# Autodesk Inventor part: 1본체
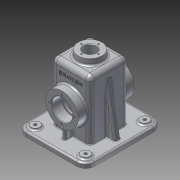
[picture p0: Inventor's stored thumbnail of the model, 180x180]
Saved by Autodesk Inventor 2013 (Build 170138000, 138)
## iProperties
Created: 2016-01
Part Number: 1본체
Material: 알루미늄 6061
Document SubType Name: Modeling
Designer: Administrator
Density: 2.71 g/cm^3
Mass: 805.142 g
Surface Area: 912.293 cm^2
Volume: 297.1 cm^3
Author: Administrator
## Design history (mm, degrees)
sketch "스케치1"
  geometry: L1 (-57.5, 65)-(57.5, 65); L2 (57.5, 65)-(57.5, -65); L3 (57.5, -65)-(-57.5, -65); L4 (-57.5, -65)-(-57.5, 65); L5 (-57.5, 65)-(57.5, -65); L6 (57.5, 65)-(-57.5, -65); 1 further point
  constraints: 12 end point, 2 midpoint, 2 parallel, 1 horizontal, 1 perpendicular
  dimensions: "d0" = 115 distance of L1.start L1.end; "d2" = 130 distance of L1.end L2.end
extrude "돌출1" new body sketch "스케치1" distance "d3" = 8; taper "d4" = 0 deg
fillet "모깎기1" dims "d5" = 15
sketch "스케치3"
  geometry: L1 (42.5, -60)-(-42.5, -60); L2 (-52.5, -50)-(-52.5, 50); L3 (-42.5, 60)-(42.5, 60); L4 (52.5, 50)-(52.5, -50); L5 (52.5, -60)-(-52.5, 60); L6 (-52.5, -60)-(52.5, 60); A1 r 10 centre (42.5, -50) between (42.5, -60) and (52.5, -50); A2 r 10 centre (42.5, 50) between (52.5, 50) and (42.5, 60); A3 r 10 centre (-42.5, 50) between (-42.5, 60) and (-52.5, 50); A4 r 10 centre (-42.5, -50) between (-52.5, -50) and (-42.5, -60); 1 further point
  constraints: 12 end point, 8 point on circle, 8 point on line, 8 tangent, 4 centre point, 3 equal radius, 2 midpoint, 2 parallel, 1 horizontal, 1 perpendicular
  dimensions: "d6" = 105 distance of L5.start L6.start; "d8" = 120 distance of L6.start L5.end; "d9" = 10 radius of A1
extrude "돌출2" join sketch "스케치3" distance "d10" = 2; taper "d11" = 0 deg
sketch "스케치7"
  geometry: L1 (-32.5, 32.5)-(32.5, 32.5); L2 (32.5, 32.5)-(32.5, -32.5); L3 (32.5, -32.5)-(-32.5, -32.5); L4 (-32.5, -32.5)-(-32.5, 32.5); L5 (-32.5, 32.5)-(32.5, -32.5); L6 (32.5, 32.5)-(-32.5, -32.5); 1 further point
  constraints: 12 end point, 2 midpoint, 2 parallel, 1 horizontal, 1 perpendicular
  dimensions: "d33" = 65 distance of L2.end L3.end; "d34" = 65 distance of L1.end L2.end
extrude "돌출4" join sketch "스케치7" distance "d35" = 100; taper "d36" = 0 deg
fillet "모깎기2" dims "d37" = 8
fillet "모깎기3" dims "d38" = 8
sketch "스케치8"
  geometry: C1 r 20 at (0, 0); 1 further point
  constraints: 1 centre point, 1 coincident
  dimensions: "d39" = 20 radius of C1
extrude "돌출5" join sketch "스케치8" distance "d40" = 10; taper "d41" = 0 deg
node "작업 평면1"
sketch "스케치10"
  geometry: L1 (-57.5, 0)-(-57.5, 8) reference; L2 (-57.5, 8)-(57.5, 8) reference; L3 (57.5, 8)-(57.5, 0) reference; L4 (52.5, 0)-(52.5, -2) reference; L5 (52.5, -2)-(-52.5, -2) reference; L6 (-52.5, -2)-(-52.5, 0) reference; L7 (-52.5, 0)-(-57.5, 0) reference; L8 (57.5, 0)-(52.5, 0) reference; C1 r 27.5 at (0, 53); 1 further point
  constraints: 1 centre point, 1 vertical alignment
  dimensions: "d44" = 55 diameter of C1; "d92" = 55 distance from line of L5 C1.centre
extrude "돌출6" join sketch "스케치10" stored distance "d45" = 10; taper "d46" = 0 deg
sketch "스케치11"
  geometry: C1 r 27.5 at (0, 0) reference; 1 further point
hole "구멍3" sketch "스케치11" at (0, 0) diameter "d47" = 30; stored, may be unused: countersink angle "d51" = 90 deg, drill point angle "d53" = 0 deg; dims "d48" = 6, "d49" = 35, "d50" = 17, "d52" = 20
sketch "스케치12"
  geometry: L1 (27.5, 27.5)-(-27.5, 27.5); L2 (-27.5, 27.5)-(-27.5, -27.5); L3 (-27.5, -27.5)-(27.5, -27.5); L4 (27.5, -27.5)-(27.5, 27.5); L5 (27.5, 27.5)-(-27.5, -27.5); L6 (-27.5, 27.5)-(27.5, -27.5); 1 further point
  constraints: 12 end point, 2 midpoint, 2 parallel, 1 horizontal, 1 perpendicular
  dimensions: "d54" = 55 distance of L2.end L3.end; "d56" = 55 distance of L3.end L1.start
extrude "돌출7" cut sketch "스케치12" distance "d57" = 105; taper "d58" = 0 deg
fillet "모깎기4" dims "d59" = 3
sketch "스케치13"
  geometry: C1 r 17.5 at (0, 0) reference; 2 further points
  constraints: 1 vertical alignment
  dimensions: "d60" = 21 distance of point (0, -21) C1.centre
hole "구멍4" sketch "스케치13" at (0, -21) diameter "d61" = 3.242; stored, may be unused: countersink angle "d65" = 90 deg, drill point angle "d67" = 118 deg; dims "d62" = 8, "d63" = 35, "d64" = 17, "d66" = 10
hole "구멍5" diameter "d73" = 21; stored, may be unused: countersink angle "d77" = 90 deg, drill point angle "d79" = 0 deg; dims "d71" = 10, "d72" = 10, "d74" = 8, "d75" = 35, "d76" = 17, "d78" = 10
feature "면 기울기1" dims angle "d80" = 5 deg
sketch "스케치14"
  geometry: C1 r 10.5 at (0, 0) reference; 1 further point
  constraints: 1 vertical alignment
  dimensions: "d81" = 14.5 distance of C1.centre point (0, -14.5)
hole "구멍6" sketch "스케치14" at (0, -14.5) diameter "d82" = 2.459; stored, may be unused: countersink angle "d86" = 90 deg, drill point angle "d88" = 118 deg; dims "d83" = 7, "d84" = 35, "d85" = 17, "d87" = 9
sketch "스케치15"
  geometry: C1 r 7.5 at (-42.5, -50); C2 r 7.5 at (42.5, -50); C3 r 7.5 at (-42.5, 50); C4 r 7.5 at (42.5, 50); A1 r 15 centre (42.5, 50) between (57.5, 50) and (42.5, 65) reference; A2 r 15 centre (-42.5, 50) between (-42.5, 65) and (-57.5, 50) reference; A3 r 15 centre (-42.5, -50) between (-57.5, -50) and (-42.5, -65) reference; A4 r 15 centre (42.5, -50) between (42.5, -65) and (57.5, -50) reference; 1 further point
  constraints: 4 centre point, 4 coincident
  dimensions: "d93" = 7.5 radius of C1; "d94" = 7.5 radius of C2; "d95" = 7.5 radius of C3; "d96" = 7.5 radius of C4
extrude "돌출8" join sketch "스케치15" distance "d97" = 3; taper "d98" = 0 deg
sketch "스케치16"
  geometry: L1 (-67, -77.5)-(-18, -77.5) reference; L2 (-15, -74.5)-(-15, -25.5) reference; L3 (-18, -22.5)-(-67, -22.5) reference; L4 (-70, -25.5)-(-70, -74.5) reference; L5 (-10, -25.5)-(-10, -74.5) reference; L6 (-18, -82.5)-(-67, -82.5) reference; L7 (-75, -74.5)-(-75, -25.5) reference; L8 (-67, -17.5)-(-18, -17.5) reference; C1 r 7.5 at (0, 0) reference; C2 r 7.5 at (-85, 0) reference; C3 r 7.5 at (-85, -100) reference; C4 r 7.5 at (0, -100) reference; C5 r 7.5 at (0, 0) reference; A1 r 3 centre (-67, -74.5) between (-70, -74.5) and (-67, -77.5) reference; A2 r 3 centre (-18, -74.5) between (-18, -77.5) and (-15, -74.5) reference; A3 r 3 centre (-18, -25.5) between (-15, -25.5) and (-18, -22.5) reference; A4 r 3 centre (-67, -25.5) between (-67, -22.5) and (-70, -25.5) reference; A5 r 8 centre (-18, -25.5) between (-10, -25.5) and (-18, -17.5) reference; A6 r 8 centre (-18, -74.5) between (-18, -82.5) and (-10, -74.5) reference; A7 r 8 centre (-67, -74.5) between (-75, -74.5) and (-67, -82.5) reference; A8 r 8 centre (-67, -25.5) between (-67, -17.5) and (-75, -25.5) reference; 1 further point
hole "구멍7" sketch "스케치16" at (-85, -100), (-85, 0), (0, 0), (0, -100) diameter "d99" = 5; stored, may be unused: countersink angle "d103" = 90 deg, drill point angle "d105" = 0 deg; dims "d100" = 5, "d101" = 35, "d102" = 17, "d104" = 9
sketch "스케치17"
  geometry: L1 (-52.5, -2)-(-52.5, 0) reference; L2 (-52.5, 0)-(-57.5, 0) reference; L3 (-57.5, 0)-(-57.5, 8) reference; L4 (-57.5, 8)-(-32.5, 8) reference; L5 (-32.5, 8)-(-32.5, 100) reference; L6 (-24.5, 108)-(-20.875, 108) reference; L7 (-20.875, 108)-(-20, 118) reference; L8 (-20, 118)-(-15.73, 118) reference; L9 (-15.73, 118)-(-15.73, 109) reference; L10 (-15.73, 109)-(-14.5, 108.261) reference; L11 (-14.5, 108.261)-(-13.271, 109) reference; L12 (-13.271, 109)-(-13.271, 118) reference; L13 (-13.271, 118)-(-10.5, 118) reference; L14 (-10.5, 118)-(-10.5, 103) reference; L15 (-10.5, 103)-(-27.5, 103) reference; L16 (-27.5, 103)-(-27.5, -2) reference; L17 (-27.5, -2)-(-52.5, -2) reference; L18 (52.5, 0)-(52.5, -2) reference; L19 (52.5, -2)-(27.5, -2) reference; L20 (27.5, -2)-(27.5, 103) reference; L21 (27.5, 103)-(10.5, 103) reference; L22 (10.5, 103)-(10.5, 118) reference; L23 (10.5, 118)-(13.271, 118) reference; L24 (13.271, 118)-(13.271, 109) reference; L25 (13.271, 109)-(14.5, 108.261) reference; L26 (14.5, 108.261)-(15.73, 109) reference; L27 (15.73, 109)-(15.73, 118) reference; L28 (15.73, 118)-(20, 118) reference; L29 (20, 118)-(20.875, 108) reference; L30 (20.875, 108)-(24.5, 108) reference; L31 (32.5, 100)-(32.5, 8) reference; L32 (32.5, 8)-(57.5, 8) reference; L33 (57.5, 8)-(57.5, 0) reference; L34 (57.5, 0)-(52.5, 0) reference; L35 (-57.5, 8)-(-42.5, 8) reference; L36 (-32.5, 100)-(-32.5, 8) reference; L37 (-32.5, 93.069)-(-47.5, 8); A1 r 8 centre (-24.5, 100) between (-24.5, 108) and (-32.5, 100) reference; A2 r 8 centre (24.5, 100) between (32.5, 100) and (24.5, 108) reference; 1 further point
  constraints: 2 end point, 2 point on line
  dimensions: "d107" = 10 distance from line of L37.end L3; "d108" = 10 deg angle of L3 L37
feature "리브1" sketch "스케치17" dims "d109" = 1, "d110" = 10, "d111" = 0, "d112" = 0, "d113" = 1, "d114" = 1
sketch "스케치18"
  geometry: L1 (0, -34.51)-(0, 0) reference; L2 (0, 0)-(49, 0) reference; L3 (49, -34.51)-(49, 0) reference; L4 (49, -92)-(49, -59.49) reference; L5 (49, -92)-(82, -92) reference; L6 (82, -92)-(82, -100) reference; L7 (82, -100)-(77, -100) reference; L8 (77, -100)-(77, -102) reference; L9 (77, -102)-(-28, -102) reference; L10 (-28, -102)-(-28, -100) reference; L11 (-28, -100)-(-33, -100) reference; L12 (-33, -100)-(-33, -92) reference; L13 (-33, -92)-(0, -92) reference; L14 (0, -92)-(49, -92) reference; L15 (0, -92)-(0, -59.49) reference; L16 (44.5, 18)-(4.5, 18) reference; L17 (-8, 0)-(-8, -92) reference; C1 r 17.5 at (24.5, -47) reference; A1 r 27.5 centre (24.5, -47) between (49, -34.51) and (0, -34.51) reference; A2 r 27.5 centre (24.5, -47) between (49, -59.49) and (49, -34.51) reference; A3 r 27.5 centre (24.5, -47) between (0, -59.49) and (49, -59.49) reference; A4 r 27.5 centre (24.5, -47) between (0, -34.51) and (0, -59.49) reference; 2 further points
  constraints: 1 other
  dimensions: "d115" = 27 distance from line of L16 point (24.5, -9); "d141" = 32.5 distance from line of point (24.5, -9) L17
feature "엠보싱1" sketch "스케치18" dims "d9" = 10, "d116" = 0.5, "d117" = 0
sketch "스케치19"
  geometry: L1 (24.5, -32.5)-(-24.5, -32.5) reference; L2 (0, -45.5)-(0, -45.5); L3 (3, -42.5)-(3, -32.5); L4 (3, -32.5)-(-3, -32.5); L5 (-3, -32.5)-(-3, -42.5); A1 r 3 centre (0, -42.5) between (-3, -42.5) and (0, -45.5); A2 r 3 centre (0, -42.5) between (0, -45.5) and (3, -42.5); 4 further points
  constraints: 8 end point, 4 point on circle, 4 point on line, 4 tangent, 2 centre point, 2 parallel, 1 collinear, 1 concentric, 1 horizontal, 1 midpoint, 1 perpendicular, 1 vertical alignment
  dimensions: "d120" = 6 distance of point (-3, -45.5) point (3, -45.5); "d130" = 3 radius of A1; "d133" = 10 distance from line of A2.centre L4
extrude "돌출9" join sketch "스케치19" stored distance "d121" = 15; taper "d122" = 0 deg
chamfer "모따기1" distance "d123" = 1; stored, may be unused: second distance "d124" = 2, angle "d125" = 45 deg
fillet "모깎기5" dims "d126" = 0.3
fillet "모깎기6" dims "d127" = 3
fillet "모깎기7" dims "d128" = 3
fillet "모깎기9" dims "d134" = 3
fillet "모깎기10" dims "d135" = 1
fillet "모깎기11" dims "d136" = 3
fillet "모깎기12" dims "d137" = 3
fillet "모깎기13" dims "d138" = 3
fillet "모깎기14" dims "d139" = 3
fillet "모깎기15" dims "d140" = 3
node "솔리드1"
mirror "대칭1"
pattern_circular "원형 패턴1" dims angle "d69" = 360 deg
mirror "대칭2"
pattern_circular "원형 패턴2" dims angle "d90" = 360 deg
mirror "대칭3"
mirror "대칭4"
node "절단 모서리 투영3"
node "절단 모서리 투영4"
node "절단 모서리 투영5"
node "절단 모서리 투영6"
other parameters: "d42" = 47.5
